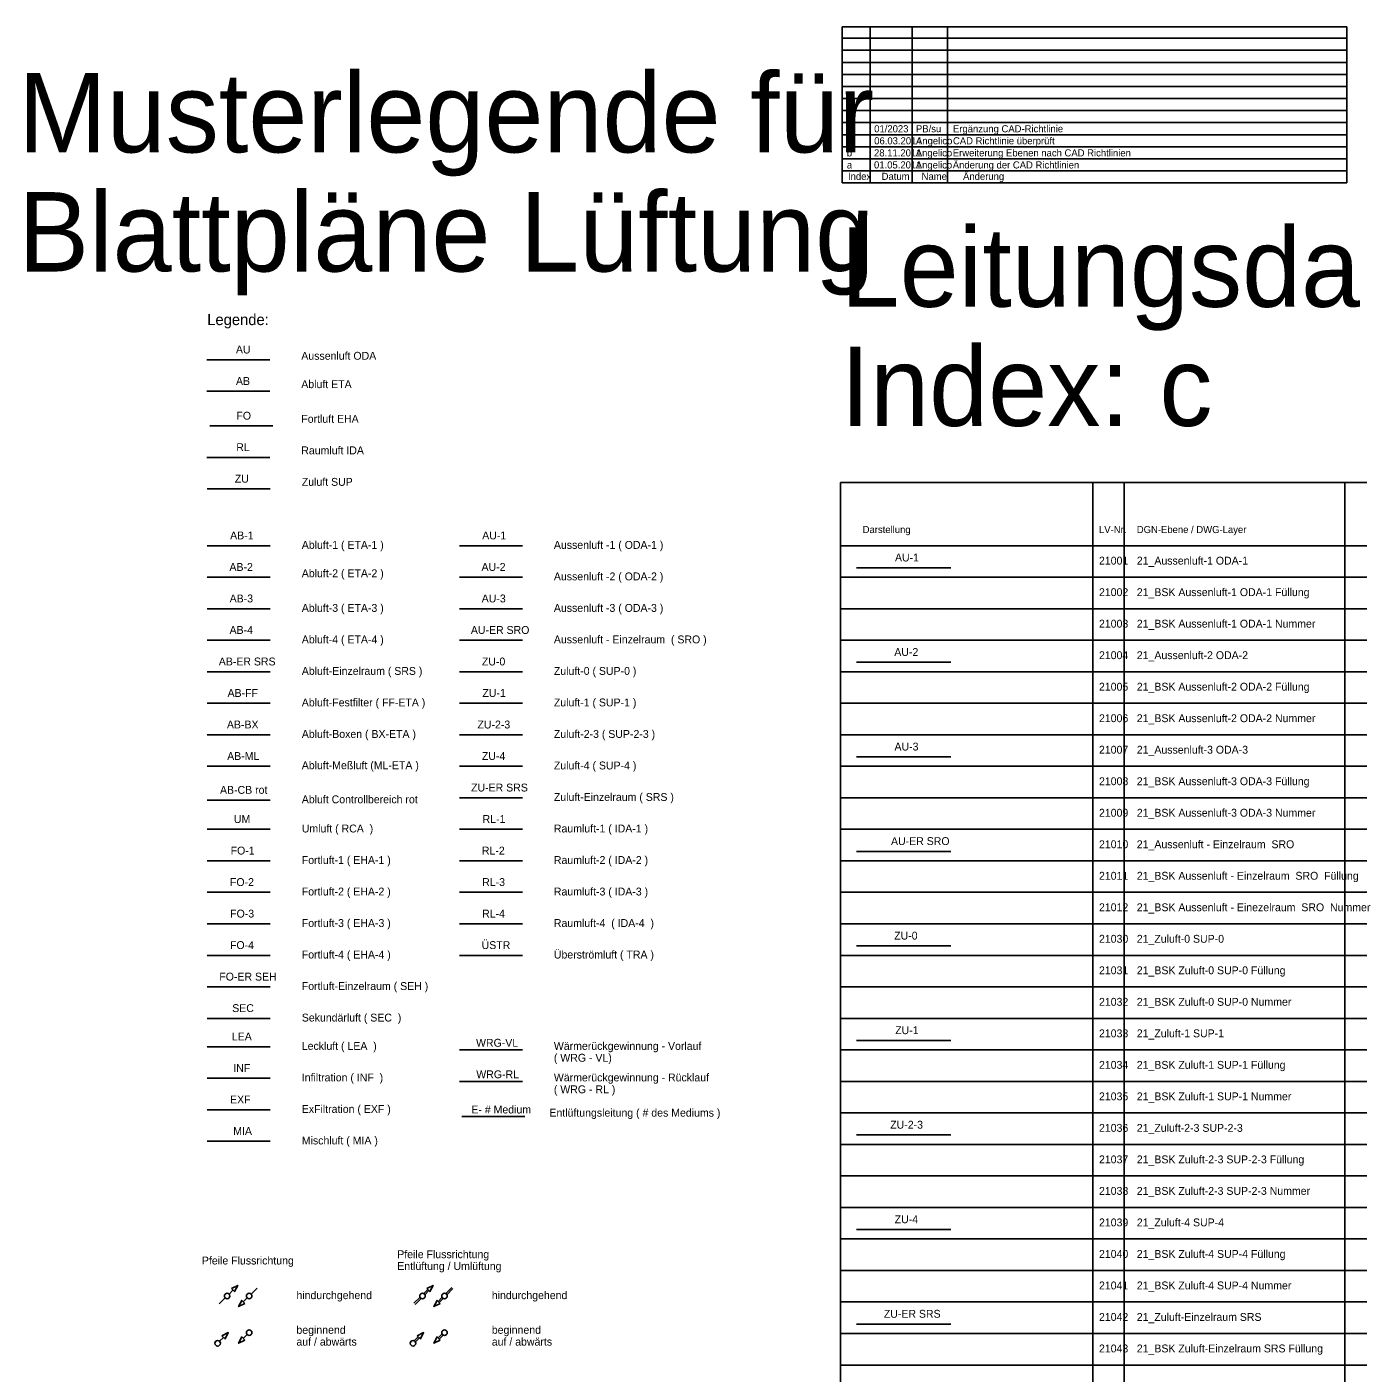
# Model space of a CAD drawing. Extents: x -12.9 to 27.6, y -77.8 to 7.2.
# Drawn here: x -12.91 to 8.21, y -14.13 to 7.23 of the extents above; entities that cross this region are included whole.
import ezdxf

# ---------------------------------------------------------------- set-up
doc = ezdxf.new("R2010")
doc.units = 0
for name, color, linetype in [('21_Abluft ETA', 7, 'Continuous'), ('21_Aussenluft - Einzelraum SRO', 7, 'Continuous'), ('21_Aussenluft ODA', 7, 'Continuous'), ('21_Aussenluft-1 ODA-1', 7, 'Continuous'), ('21_Aussenluft-2 ODA-2', 7, 'Continuous'), ('21_Aussenluft-3 ODA-3', 7, 'Continuous'), ('21_Fortluft EHA', 7, 'Continuous'), ('21_Raumluft-1 IDA-1', 7, 'Continuous'), ('21_Zuluft-0 SUP-0', 7, 'Continuous'), ('21_Zuluft-1 SUP-1', 7, 'Continuous'), ('21_Zuluft-2-3 SUP-2-3', 7, 'Continuous'), ('21_Zuluft-4 SUP-4', 7, 'Continuous'), ('21_Zuluft-Einzelraum SRS', 7, 'Continuous'), ('90_Plankopf', 7, 'Continuous'), ('Default', 7, 'Continuous')]:
    doc.layers.add(name, color=color, linetype=linetype)

msp = doc.modelspace()

# ---------------------------------------------------------------- linework, layer by layer
at = {"layer": '21_Abluft ETA'}
msp.add_line((-10.058, 1.45), (-9.058, 1.45), dxfattribs=at)
at = {"layer": '21_Aussenluft - Einzelraum SRO'}
msp.add_line((0.25, -5.85), (1.75, -5.85), dxfattribs=at)
at = {"layer": '21_Aussenluft ODA'}
msp.add_line((-10.058, 1.95), (-9.058, 1.95), dxfattribs=at)
at = {"layer": '21_Aussenluft-1 ODA-1'}
msp.add_line((0.25, -1.35), (1.75, -1.35), dxfattribs=at)
at = {"layer": '21_Aussenluft-2 ODA-2'}
msp.add_line((0.25, -2.85), (1.75, -2.85), dxfattribs=at)
at = {"layer": '21_Aussenluft-3 ODA-3'}
msp.add_line((0.25, -4.35), (1.75, -4.35), dxfattribs=at)
at = {"layer": '21_Fortluft EHA'}
msp.add_line((-10.008, 0.9), (-9.008, 0.9), dxfattribs=at)
at = {"layer": '21_Raumluft-1 IDA-1'}
msp.add_line((-10.058, 0.4), (-9.058, 0.4), dxfattribs=at)
at = {"layer": '21_Zuluft-0 SUP-0'}
msp.add_line((0.25, -7.35), (1.75, -7.35), dxfattribs=at)
at = {"layer": '21_Zuluft-1 SUP-1'}
msp.add_line((0.25, -8.85), (1.75, -8.85), dxfattribs=at)
at = {"layer": '21_Zuluft-2-3 SUP-2-3'}
for p, q in [((-10.05, -0.1), (-9.05, -0.1)), ((0.25, -10.35), (1.75, -10.35))]:
    msp.add_line(p, q, dxfattribs=at)
at = {"layer": '21_Zuluft-4 SUP-4'}
msp.add_line((0.25, -11.85), (1.75, -11.85), dxfattribs=at)
at = {"layer": '21_Zuluft-Einzelraum SRS'}
msp.add_line((0.25, -13.35), (1.75, -13.35), dxfattribs=at)
at = {"layer": '90_Plankopf'}
for p, q in [((-10.05, -1), (-9.05, -1)), ((-6.05, -1), (-5.05, -1)), ((-10.05, -1.5), (-9.05, -1.5)), ((-6.05, -1.5), (-5.05, -1.5)), ((-10.05, -2), (-9.05, -2)), ((-6.05, -2), (-5.05, -2)), ((-10.05, -2.5), (-9.05, -2.5)), ((-6.05, -2.5), (-5.05, -2.5)), ((-10.05, -3), (-9.05, -3)), ((-6.05, -3), (-5.05, -3)), ((-10.05, -3.5), (-9.05, -3.5)), ((-6.05, -3.5), (-5.05, -3.5)), ((-10.05, -4), (-9.05, -4)), ((-6.05, -4), (-5.05, -4)), ((-10.05, -4.5), (-9.05, -4.5)), ((-6.05, -4.5), (-5.05, -4.5)), ((-10.05, -5.037), (-9.05, -5.037)), ((-6.05, -5), (-5.05, -5)), ((-10.05, -5.5), (-9.05, -5.5)), ((-6.05, -5.5), (-5.05, -5.5)), ((-10.05, -6), (-9.05, -6)), ((-6.05, -6), (-5.05, -6)), ((-10.05, -6.5), (-9.05, -6.5)), ((-6.05, -6.5), (-5.05, -6.5)), ((-10.05, -7), (-9.05, -7)), ((-6.05, -7), (-5.05, -7)), ((-10.05, -7.5), (-9.05, -7.5)), ((-6.05, -7.5), (-5.05, -7.5)), ((-10.05, -8), (-9.05, -8)), ((-10.05, -8.5), (-9.05, -8.5)), ((-10.05, -8.95), (-9.05, -8.95)), ((-6.05, -9), (-5.05, -9)), ((-10.05, -9.45), (-9.05, -9.45)), ((-6.05, -9.5), (-5.05, -9.5)), ((-10.05, -9.95), (-9.05, -9.95)), ((-6.009, -10.059), (-5.009, -10.059)), ((-10.05, -10.45), (-9.05, -10.45)), ((-9.704, -12.874), (-9.642, -12.811)), ((-9.26, -12.779), (-9.354, -12.874)), ((-6.615, -12.866), (-6.551, -12.802)), ((-6.169, -12.77), (-6.265, -12.866)), ((-6.151, -12.788), (-6.247, -12.884)), ((-9.861, -13.03), (-9.766, -12.936)), ((-9.416, -12.936), (-9.479, -12.998)), ((-6.77, -13.021), (-6.674, -12.926)), ((-6.752, -13.039), (-6.656, -12.943)), ((-6.597, -12.884), (-6.533, -12.82)), ((-6.324, -12.926), (-6.388, -12.99)), ((-6.306, -12.943), (-6.37, -13.007)), ((-9.854, -13.624), (-9.792, -13.561)), ((-9.416, -13.517), (-9.479, -13.58)), ((-6.765, -13.616), (-6.701, -13.552)), ((-6.747, -13.634), (-6.683, -13.57)), ((-6.324, -13.507), (-6.388, -13.571)), ((-6.306, -13.525), (-6.37, -13.589))]:
    msp.add_line(p, q, dxfattribs=at)
for points in [[(-9.667, -12.786), (-9.617, -12.836), (-9.567, -12.736)], [(-6.567, -12.786), (-6.517, -12.836), (-6.467, -12.736)], [(-9.454, -13.023), (-9.504, -12.974), (-9.554, -13.073)], [(-6.354, -13.023), (-6.404, -12.974), (-6.454, -13.073)], [(-9.817, -13.536), (-9.767, -13.586), (-9.717, -13.486)], [(-9.454, -13.605), (-9.504, -13.555), (-9.554, -13.655)], [(-6.717, -13.536), (-6.667, -13.586), (-6.617, -13.486)], [(-6.354, -13.605), (-6.404, -13.555), (-6.454, -13.655)]]:
    msp.add_lwpolyline(points, close=True, dxfattribs=at)
for centre in [(-9.735, -12.905), (-9.385, -12.905), (-6.635, -12.905), (-6.285, -12.905), (-9.385, -13.486), (-6.285, -13.486), (-9.885, -13.655), (-6.785, -13.655)]:
    msp.add_circle(centre, 0.0438, dxfattribs=at)
at = {"layer": 'Default'}
for p, q in [((0.026, 4.756), (0.026, 7.231)), ((0.026, 7.231), (8.031, 7.231)), ((0.026, 7.051), (8.031, 7.051)), ((0.471, 4.756), (0.471, 7.231)), ((1.138, 4.756), (1.138, 7.231)), ((1.694, 4.756), (1.694, 7.231)), ((8.031, 4.756), (8.031, 7.231)), ((0.026, 6.86), (8.031, 6.86)), ((0.026, 6.669), (8.031, 6.669)), ((0.026, 6.478), (8.031, 6.478)), ((0.026, 6.286), (8.031, 6.286)), ((0.026, 6.095), (8.031, 6.095)), ((0.026, 5.904), (8.031, 5.904)), ((0.026, 5.713), (8.031, 5.713)), ((0.026, 5.521), (8.031, 5.521)), ((0.026, 5.33), (8.031, 5.33)), ((0.026, 5.139), (8.031, 5.139)), ((0.026, 4.948), (8.031, 4.948)), ((0.026, 4.756), (8.031, 4.756)), ((0.026, 4.756), (8.031, 4.756)), ((0, 0), (0, -73.5)), ((0, 0), (16.8, 0)), ((4, 0), (4, -73.5)), ((4.5, 0), (4.5, -73.5)), ((8, 0), (8, -73.5)), ((0, -1), (16.8, -1)), ((0, -1.5), (16.8, -1.5)), ((0, -2), (16.8, -2)), ((0, -2.5), (16.8, -2.5)), ((0, -3), (16.8, -3)), ((0, -3.5), (16.8, -3.5)), ((0, -4), (16.8, -4)), ((0, -4.5), (16.8, -4.5)), ((0, -5), (16.8, -5)), ((0, -5.5), (16.8, -5.5)), ((0, -6), (16.8, -6)), ((0, -6.5), (16.8, -6.5)), ((0, -7), (16.8, -7)), ((0, -7.5), (16.8, -7.5)), ((0, -8), (16.8, -8)), ((0, -8.5), (16.8, -8.5)), ((0, -9), (16.8, -9)), ((0, -9.5), (16.8, -9.5)), ((0, -10), (16.8, -10)), ((0, -10.5), (16.8, -10.5)), ((0, -11), (16.8, -11)), ((0, -11.5), (16.8, -11.5)), ((0, -12), (16.8, -12)), ((0, -12.5), (16.8, -12.5)), ((0, -13), (16.8, -13)), ((0, -13.5), (16.8, -13.5)), ((0, -14), (16.8, -14))]:
    msp.add_line(p, q, dxfattribs=at)

# ---------------------------------------------------------------- texts
at = {"layer": '21_Abluft ETA'}
msp.add_text('AB', height=0.125, dxfattribs=at).set_placement((-9.595, 1.55))
at = {"layer": '21_Aussenluft - Einzelraum SRO'}
msp.add_text('AU-ER SRO', height=0.125, dxfattribs=at).set_placement((0.8, -5.75))
at = {"layer": '21_Aussenluft ODA'}
msp.add_text('AU', height=0.125, dxfattribs=at).set_placement((-9.595, 2.05))
at = {"layer": '21_Aussenluft-1 ODA-1'}
msp.add_text('AU-1', height=0.125, dxfattribs=at).set_placement((0.863, -1.25))
at = {"layer": '21_Aussenluft-2 ODA-2'}
msp.add_text('AU-2', height=0.125, dxfattribs=at).set_placement((0.852, -2.75))
at = {"layer": '21_Aussenluft-3 ODA-3'}
msp.add_text('AU-3', height=0.125, dxfattribs=at).set_placement((0.855, -4.25))
at = {"layer": '21_Fortluft EHA'}
msp.add_text('FO', height=0.125, dxfattribs=at).set_placement((-9.587, 1))
at = {"layer": '21_Raumluft-1 IDA-1'}
msp.add_text('RL', height=0.125, dxfattribs=at).set_placement((-9.589, 0.5))
at = {"layer": '21_Zuluft-0 SUP-0'}
msp.add_text('ZU-0', height=0.125, dxfattribs=at).set_placement((0.85, -7.25))
at = {"layer": '21_Zuluft-1 SUP-1'}
msp.add_text('ZU-1', height=0.125, dxfattribs=at).set_placement((0.866, -8.75))
at = {"layer": '21_Zuluft-2-3 SUP-2-3'}
for s, p in [('ZU', (-9.613, 0)), ('ZU-2-3', (0.787, -10.25))]:
    msp.add_text(s, height=0.125, dxfattribs=at).set_placement(p)
at = {"layer": '21_Zuluft-4 SUP-4'}
msp.add_text('ZU-4', height=0.125, dxfattribs=at).set_placement((0.858, -11.75))
at = {"layer": '21_Zuluft-Einzelraum SRS'}
msp.add_text('ZU-ER SRS', height=0.125, dxfattribs=at).set_placement((0.686, -13.25))
at = {"layer": '90_Plankopf'}
for s, height, p in [('Legende:', 0.175, (-10.05, 2.5)), ('AB-1', 0.125, (-9.687, -0.9)), ('AU-1', 0.125, (-5.687, -0.9)), ('Abluft-1 ( ETA-1 )', 0.125, (-8.55, -1.05)), ('Aussenluft -1 ( ODA-1 )', 0.125, (-4.55, -1.05)), ('AB-2', 0.125, (-9.698, -1.4)), ('AU-2', 0.125, (-5.698, -1.4)), ('Abluft-2 ( ETA-2 )', 0.125, (-8.55, -1.5)), ('Aussenluft -2 ( ODA-2 )', 0.125, (-4.55, -1.55)), ('AB-3', 0.125, (-9.695, -1.9)), ('Abluft-3 ( ETA-3 )', 0.125, (-8.55, -2.05)), ('AU-3', 0.125, (-5.695, -1.9)), ('Aussenluft -3 ( ODA-3 )', 0.125, (-4.55, -2.05)), ('AB-4', 0.125, (-9.696, -2.4)), ('AU-ER SRO', 0.125, (-5.867, -2.4)), ('Abluft-4 ( ETA-4 )', 0.125, (-8.55, -2.55)), ('Aussenluft - Einzelraum  ( SRO )', 0.125, (-4.55, -2.55)), ('AB-ER SRS', 0.125, (-9.867, -2.9)), ('ZU-0', 0.125, (-5.692, -2.9)), ('Abluft-Einzelraum ( SRS )', 0.125, (-8.55, -3.05)), ('Zuluft-0 ( SUP-0 )', 0.125, (-4.55, -3.05)), ('AB-FF', 0.125, (-9.728, -3.4)), ('ZU-1', 0.125, (-5.684, -3.4)), ('Abluft-Festfilter ( FF-ETA )', 0.125, (-8.55, -3.55)), ('Zuluft-1 ( SUP-1 )', 0.125, (-4.55, -3.55)), ('AB-BX', 0.125, (-9.738, -3.9)), ('ZU-2-3', 0.125, (-5.763, -3.9)), ('Abluft-Boxen ( BX-ETA )', 0.125, (-8.55, -4.05)), ('Zuluft-2-3 ( SUP-2-3 )', 0.125, (-4.55, -4.05)), ('AB-ML', 0.125, (-9.734, -4.4)), ('Abluft-Meßluft (ML-ETA )', 0.125, (-8.55, -4.546)), ('ZU-4', 0.125, (-5.692, -4.4)), ('Zuluft-4 ( SUP-4 )', 0.125, (-4.55, -4.55)), ('AB-CB rot', 0.125, (-9.848, -4.937)), ('ZU-ER SRS', 0.125, (-5.864, -4.9)), ('Abluft Controllbereich rot', 0.125, (-8.55, -5.087)), ('Zuluft-Einzelraum ( SRS )', 0.125, (-4.55, -5.05)), ('UM', 0.125, (-9.627, -5.4)), ('RL-1', 0.125, (-5.681, -5.4)), ('Umluft ( RCA  )', 0.125, (-8.55, -5.55)), ('Raumluft-1 ( IDA-1 )', 0.125, (-4.55, -5.55)), ('FO-1', 0.125, (-9.679, -5.9)), ('Fortluft-1 ( EHA-1 )', 0.125, (-8.55, -6.05)), ('RL-2', 0.125, (-5.692, -5.9)), ('Raumluft-2 ( IDA-2 )', 0.125, (-4.55, -6.05)), ('FO-2', 0.125, (-9.69, -6.4)), ('RL-3', 0.125, (-5.688, -6.4)), ('Fortluft-2 ( EHA-2 )', 0.125, (-8.55, -6.55)), ('Raumluft-3 ( IDA-3 )', 0.125, (-4.55, -6.55)), ('FO-3', 0.125, (-9.687, -6.9)), ('RL-4', 0.125, (-5.689, -6.9)), ('Fortluft-3 ( EHA-3 )', 0.125, (-8.55, -7.05)), ('Raumluft-4  ( IDA-4  )', 0.125, (-4.55, -7.05)), ('ÜSTR', 0.125, (-5.696, -7.4)), ('FO-4', 0.125, (-9.689, -7.4)), ('Fortluft-4 ( EHA-4 )', 0.125, (-8.55, -7.55)), ('Überströmluft ( TRA )', 0.125, (-4.55, -7.55)), ('FO-ER SEH', 0.125, (-9.859, -7.9)), ('Fortluft-Einzelraum ( SEH )', 0.125, (-8.55, -8.05)), ('SEC', 0.125, (-9.654, -8.4)), ('Sekundärluft ( SEC  )', 0.125, (-8.55, -8.55)), ('LEA', 0.125, (-9.659, -8.85)), ('Leckluft ( LEA  )', 0.125, (-8.55, -9)), ('WRG-VL', 0.125, (-5.785, -8.95)), ('Wärmerückgewinnung - Vorlauf ', 0.125, (-4.55, -9)), ('( WRG - VL)', 0.125, (-4.55, -9.188)), ('INF', 0.125, (-9.637, -9.35)), ('Infiltration ( INF  )', 0.125, (-8.55, -9.5)), ('WRG-RL', 0.125, (-5.781, -9.45)), ('Wärmerückgewinnung - Rücklauf ', 0.125, (-4.55, -9.5)), ('( WRG - RL )', 0.125, (-4.55, -9.688)), ('EXF ', 0.125, (-9.688, -9.85)), ('ExFiltration ( EXF )', 0.125, (-8.55, -10)), ('E- # Medium', 0.125, (-5.859, -10.009)), (' Entlüftungsleitung ( # des Mediums )', 0.125, (-4.667, -10.059)), ('MIA', 0.125, (-9.638, -10.35)), ('Mischluft ( MIA )', 0.125, (-8.55, -10.5)), ('Pfeile Flussrichtung', 0.125, (-7.035, -12.305)), ('Pfeile Flussrichtung', 0.125, (-10.135, -12.405)), ('Entlüftung / Umlüftung', 0.125, (-7.035, -12.492)), ('hindurchgehend', 0.125, (-8.635, -12.955)), ('hindurchgehend', 0.125, (-5.535, -12.955)), ('beginnend', 0.125, (-8.635, -13.505)), ('beginnend', 0.125, (-5.535, -13.505)), ('auf / abwärts', 0.125, (-8.635, -13.692)), ('auf / abwärts', 0.125, (-5.535, -13.692))]:
    msp.add_text(s, height=height, dxfattribs=at).set_placement(p)
at = {"layer": 'Default'}
for s, height, p in [('Musterlegende für ', 1.26, (-13.05, 5.24)), ('c     ', 0.1125, (0.102, 5.559)), ('01/2023   ', 0.1125, (0.533, 5.559)), ('PB/su   ', 0.1125, (1.196, 5.559)), ('Ergänzung CAD-Richtlinie                                                                        ', 0.1125, (1.783, 5.559)), ('-     ', 0.1125, (0.102, 5.368)), ('06.03.2014', 0.1125, (0.533, 5.368)), ('Angelico', 0.1125, (1.196, 5.368)), ('CAD Richtlinie überprüft                                                                        ', 0.1125, (1.783, 5.368)), ('b     ', 0.1125, (0.099, 5.176)), ('28.11.2011', 0.1125, (0.53, 5.176)), ('Angelico', 0.1125, (1.193, 5.176)), ('Erweiterung Ebenen nach CAD Richtlinien                                                         ', 0.1125, (1.78, 5.176)), ('a     ', 0.1125, (0.099, 4.985)), ('Index', 0.1125, (0.117, 4.804)), ('01.05.2011', 0.1125, (0.53, 4.985)), ('Datum', 0.1125, (0.651, 4.804)), ('Angelico', 0.1125, (1.193, 4.985)), ('Name', 0.1125, (1.285, 4.804)), ('Änderung der CAD Richtlinien                                                                    ', 0.1125, (1.78, 4.985)), ('Änderung', 0.1125, (1.943, 4.804)), ('Blattpläne Lüftung', 1.26, (-13.05, 3.35)), ('Leitungsdarstellung: Lüftung', 1.26, (0, 2.79)), ('Index: c', 1.26, (0, 0.9)), ('Aussenluft ODA', 0.125, (-8.558, 1.95)), ('Abluft ETA', 0.125, (-8.558, 1.5)), ('Fortluft EHA', 0.125, (-8.558, 0.95)), ('Raumluft IDA', 0.125, (-8.558, 0.45)), ('Zuluft SUP', 0.125, (-8.55, -0.05)), ('Darstellung', 0.1125, (0.35, -0.8)), ('LV-Nr.', 0.1125, (4.1, -0.8)), ('DGN-Ebene / DWG-Layer', 0.1125, (4.7, -0.8)), ('21001', 0.125, (4.1, -1.3)), ('21_Aussenluft-1 ODA-1', 0.125, (4.7, -1.3)), ('21002', 0.125, (4.1, -1.8)), ('21_BSK Aussenluft-1 ODA-1 Füllung', 0.125, (4.7, -1.8)), ('21003', 0.125, (4.1, -2.3)), ('21_BSK Aussenluft-1 ODA-1 Nummer', 0.125, (4.7, -2.3)), ('21004', 0.125, (4.1, -2.8)), ('21_Aussenluft-2 ODA-2', 0.125, (4.7, -2.8)), ('21005', 0.125, (4.1, -3.3)), ('21_BSK Aussenluft-2 ODA-2 Füllung', 0.125, (4.7, -3.3)), ('21006', 0.125, (4.1, -3.8)), ('21_BSK Aussenluft-2 ODA-2 Nummer', 0.125, (4.7, -3.8)), ('21007', 0.125, (4.1, -4.3)), ('21_Aussenluft-3 ODA-3', 0.125, (4.7, -4.3)), ('21008', 0.125, (4.1, -4.8)), ('21_BSK Aussenluft-3 ODA-3 Füllung', 0.125, (4.7, -4.8)), ('21009', 0.125, (4.1, -5.3)), ('21_BSK Aussenluft-3 ODA-3 Nummer', 0.125, (4.7, -5.3)), ('21010', 0.125, (4.1, -5.8)), ('21_Aussenluft - Einzelraum  SRO ', 0.125, (4.7, -5.8)), ('21011', 0.125, (4.1, -6.3)), ('21_BSK Aussenluft - Einzelraum  SRO  Füllung', 0.125, (4.7, -6.3)), ('21012', 0.125, (4.1, -6.8)), ('21_BSK Aussenluft - Einezelraum  SRO  Nummer', 0.125, (4.7, -6.8)), ('21030', 0.125, (4.1, -7.3)), ('21_Zuluft-0 SUP-0', 0.125, (4.7, -7.3)), ('21031', 0.125, (4.1, -7.8)), ('21_BSK Zuluft-0 SUP-0 Füllung', 0.125, (4.7, -7.8)), ('21032', 0.125, (4.1, -8.3)), ('21_BSK Zuluft-0 SUP-0 Nummer', 0.125, (4.7, -8.3)), ('21033', 0.125, (4.1, -8.8)), ('21_Zuluft-1 SUP-1', 0.125, (4.7, -8.8)), ('21034', 0.125, (4.1, -9.3)), ('21_BSK Zuluft-1 SUP-1 Füllung', 0.125, (4.7, -9.3)), ('21035', 0.125, (4.1, -9.8)), ('21_BSK Zuluft-1 SUP-1 Nummer', 0.125, (4.7, -9.8)), ('21036', 0.125, (4.1, -10.3)), ('21_Zuluft-2-3 SUP-2-3', 0.125, (4.7, -10.3)), ('21037', 0.125, (4.1, -10.8)), ('21_BSK Zuluft-2-3 SUP-2-3 Füllung', 0.125, (4.7, -10.8)), ('21038', 0.125, (4.1, -11.3)), ('21_BSK Zuluft-2-3 SUP-2-3 Nummer', 0.125, (4.7, -11.3)), ('21039', 0.125, (4.1, -11.8)), ('21_Zuluft-4 SUP-4', 0.125, (4.7, -11.8)), ('21040', 0.125, (4.1, -12.3)), ('21_BSK Zuluft-4 SUP-4 Füllung', 0.125, (4.7, -12.3)), ('21041', 0.125, (4.1, -12.8)), ('21_BSK Zuluft-4 SUP-4 Nummer', 0.125, (4.7, -12.8)), ('21042', 0.125, (4.1, -13.3)), ('21_Zuluft-Einzelraum SRS', 0.125, (4.7, -13.3)), ('21_BSK Zuluft-Einzelraum SRS Füllung', 0.125, (4.7, -13.8)), ('21043', 0.125, (4.1, -13.8))]:
    msp.add_text(s, height=height, dxfattribs=at).set_placement(p)

doc.saveas('drawing.dxf')
